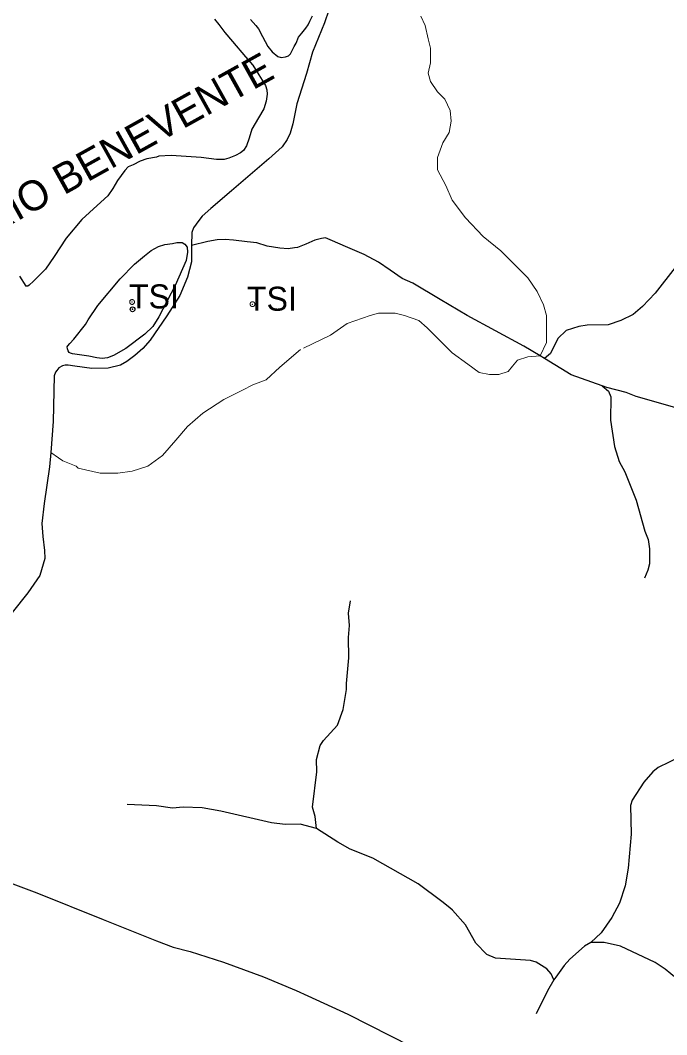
# Model space of a CAD drawing. Extents: x 317.8 to 344.1, y 7676.8 to 7704.8.
# Drawn here: x 328.24 to 330.394, y 7697.935 to 7701.313 of the extents above; entities that cross this region are included whole.
import ezdxf
from ezdxf.enums import TextEntityAlignment as Align

# ---------------------------------------------------------------- set-up
doc = ezdxf.new("R2010")
doc.units = 0
doc.header["$LTSCALE"] = 0.032
doc.header["$PDMODE"] = 32
doc.header["$PDSIZE"] = 0.016
doc.linetypes.add('SHORT_DASHED', pattern=[2.7, 1.5, -1.2])
for name, color, linetype, lineweight in [('2', 7, 'Continuous', 25), ('21', 7, 'SHORT_DASHED', 13), ('7', 7, 'Continuous', 25)]:
    doc.layers.add(name, color=color, linetype=linetype, lineweight=lineweight)
doc.layers.add('54', color=7, linetype='Continuous')
doc.layers.add('61', color=7, linetype='Continuous')

msp = doc.modelspace()

# ---------------------------------------------------------------- linework, layer by layer
at = {"layer": '2'}
for points in [[(329.2171, 7701.5954), (329.2251, 7701.5909), (329.2353, 7701.5818), (329.2524, 7701.5499), (329.2672, 7701.51), (329.2729, 7701.4668), (329.2729, 7701.4087), (329.2672, 7701.3472), (329.2536, 7701.305), (329.2137, 7701.2071), (329.1932, 7701.1365), (329.1613, 7701.0352), (329.1476, 7700.968), (329.1385, 7700.9372), (329.1294, 7700.9167), (329.1123, 7700.8917), (329.0679, 7700.8518), (328.9438, 7700.7459), (328.8743, 7700.6867), (328.8459, 7700.6605), (328.8345, 7700.6468), (328.8163, 7700.6218), (328.8117, 7700.607), (328.8106, 7700.5637)], [(328.8867, 7701.317), (328.9013, 7701.2992), (328.9212, 7701.2723), (328.947, 7701.243), (328.9903, 7701.1915), (329.0149, 7701.1634), (329.0348, 7701.1318), (329.057, 7701.0967), (329.0612, 7701.0814), (329.0617, 7701.0674), (329.0593, 7701.044), (329.0512, 7701.0183), (329.0336, 7700.989), (329.0114, 7700.9504), (329.002, 7700.9211), (328.9938, 7700.8954), (328.9833, 7700.8802), (328.9739, 7700.872), (328.9563, 7700.8626), (328.9341, 7700.8544), (328.9189, 7700.8497), (328.8931, 7700.8497), (328.8428, 7700.8568), (328.7422, 7700.8626)], [(329.0064, 7701.3164), (329.0247, 7701.2959), (329.0338, 7701.2845), (329.0463, 7701.2595), (329.0645, 7701.2265), (329.0793, 7701.2083), (329.0975, 7701.1923), (329.1089, 7701.19), (329.1237, 7701.1912), (329.1328, 7701.1946), (329.1397, 7701.2014), (329.142, 7701.206), (329.1522, 7701.2265), (329.159, 7701.2367), (329.167, 7701.2572), (329.1773, 7701.2709), (329.1909, 7701.2868), (329.1989, 7701.2982), (329.2046, 7701.3107), (329.2137, 7701.3278)], [(328.7422, 7700.8626), (328.7012, 7700.8603), (328.693, 7700.8579), (328.6614, 7700.8521), (328.6392, 7700.8439), (328.6157, 7700.8322)], [(328.6157, 7700.8322), (328.5994, 7700.8252), (328.5877, 7700.8135), (328.5631, 7700.7795), (328.5479, 7700.7526), (328.5315, 7700.7292), (328.4952, 7700.6964), (328.4449, 7700.6496), (328.3922, 7700.5876), (328.3524, 7700.5267), (328.3231, 7700.4846), (328.2833, 7700.4442), (328.2688, 7700.431), (328.2648, 7700.4282), (328.2615, 7700.4276), (328.2576, 7700.4284)], [(328.8106, 7700.5637), (328.8106, 7700.509), (328.7969, 7700.4578), (328.7707, 7700.3963), (328.7274, 7700.3291), (328.6728, 7700.2483), (328.6477, 7700.2198), (328.6215, 7700.197), (328.5942, 7700.1765), (328.5737, 7700.1651), (328.5327, 7700.1549), (328.478, 7700.1537), (328.4211, 7700.1617), (328.3995, 7700.1651), (328.3892, 7700.1651), (328.3801, 7700.1629), (328.3676, 7700.156), (328.3608, 7700.1469), (328.3573, 7700.1412), (328.3528, 7700.1287), (328.3494, 7699.9772), (328.3408, 7699.8737)], [(328.2373, 7700.4609), (328.2576, 7700.4284)], [(328.3408, 7699.8737), (328.3368, 7699.8258), (328.3186, 7699.7039), (328.3118, 7699.6379), (328.3152, 7699.5946), (328.3198, 7699.5479), (328.3209, 7699.5206), (328.3163, 7699.5024), (328.305, 7699.4637), (328.2651, 7699.4067), (328.2127, 7699.3407)], [(328.0088, 7698.5018), (328.0345, 7698.4948), (328.1338, 7698.4678), (328.295, 7698.4078), (328.516, 7698.319), (328.6937, 7698.2477), (328.7485, 7698.226), (328.8053, 7698.2116), (328.9169, 7698.1764), (329.0501, 7698.1279), (329.1586, 7698.0824), (329.1976, 7698.0644), (329.3311, 7698.0029), (329.5429, 7697.8954)]]:
    msp.add_lwpolyline(points, dxfattribs=at)
msp.add_lwpolyline([(328.4974, 7700.3635), (328.572, 7700.4518), (328.6203, 7700.5015), (328.6534, 7700.5291), (328.6755, 7700.5471), (328.7003, 7700.5595), (328.721, 7700.5664), (328.7473, 7700.5705), (328.7611, 7700.5733), (328.779, 7700.5733), (328.7873, 7700.5678), (328.7956, 7700.5581), (328.7969, 7700.5415), (328.7928, 7700.5139), (328.7555, 7700.4297), (328.7017, 7700.3262), (328.681, 7700.2931), (328.6548, 7700.2683), (328.5913, 7700.2199), (328.5499, 7700.1965), (328.5306, 7700.1896), (328.5127, 7700.1875), (328.4947, 7700.1896), (328.4684, 7700.1951), (328.4367, 7700.1992), (328.4132, 7700.202), (328.4064, 7700.2046), (328.4022, 7700.2075), (328.3988, 7700.2122), (328.3968, 7700.2188), (328.3962, 7700.2257), (328.3985, 7700.2293), (328.4041, 7700.2365), (328.4179, 7700.2517), (328.4571, 7700.3001), (328.4657, 7700.3152)], close=True, dxfattribs=at)
at = {"layer": '21'}
for points in [[(329.5748, 7701.3273), (329.5887, 7701.2961), (329.599, 7701.2512), (329.606, 7701.22), (329.606, 7701.1716), (329.599, 7701.137), (329.606, 7701.1093), (329.6302, 7701.0747), (329.6544, 7701.0504), (329.6717, 7701.0124), (329.6752, 7700.9778), (329.6683, 7700.9397), (329.6475, 7700.9051), (329.6302, 7700.8567), (329.6302, 7700.8151), (329.6579, 7700.7632), (329.6786, 7700.7148), (329.7236, 7700.6559), (329.7824, 7700.5937), (329.8413, 7700.5452), (329.8932, 7700.4933), (329.9313, 7700.4552), (329.9624, 7700.4102), (329.9832, 7700.3653), (329.9935, 7700.3307), (329.9935, 7700.3064), (329.9935, 7700.2787), (329.9935, 7700.2407), (329.9716, 7700.1954)], [(329.9716, 7700.1954), (329.9313, 7700.1922), (329.8966, 7700.1818), (329.8793, 7700.1611), (329.8655, 7700.1438), (329.8344, 7700.1334), (329.8032, 7700.1334), (329.7686, 7700.1403), (329.7305, 7700.168), (329.6786, 7700.2061), (329.6302, 7700.2545), (329.5956, 7700.2891), (329.5679, 7700.3133), (329.5194, 7700.3307), (329.4883, 7700.3376), (329.4329, 7700.3376), (329.4053, 7700.3307), (329.3291, 7700.303), (329.2738, 7700.2649), (329.1734, 7700.2165), (329.1042, 7700.1576), (329.0592, 7700.1161), (329.0142, 7700.0988), (328.9796, 7700.0815), (328.9173, 7700.0503), (328.8481, 7700.0054), (328.7962, 7699.9604), (328.7581, 7699.9154), (328.7131, 7699.8635), (328.6647, 7699.8289), (328.6128, 7699.8116), (328.5643, 7699.8046), (328.5055, 7699.8046), (328.4328, 7699.822), (328.4259, 7699.8289), (328.3809, 7699.8462), (328.3671, 7699.8566), (328.3408, 7699.8737)]]:
    msp.add_lwpolyline(points, dxfattribs=at)
for p in [(328.6121, 7700.3752), (329.0133, 7700.3679)]:
    msp.add_point(p, dxfattribs=at)
at = {"layer": '54'}
msp.add_point((328.6137, 7700.3509), dxfattribs=at)
at = {"layer": '7'}
for p, q in [((329.9716, 7700.1954), (329.9176, 7700.2279)), ((329.986, 7700.1867), (329.9716, 7700.1954))]:
    msp.add_line(p, q, dxfattribs=at)
for points in [[(329.9176, 7700.2279), (329.7287, 7700.3302), (329.6386, 7700.3832), (329.5475, 7700.438), (329.5117, 7700.4538), (329.4718, 7700.4807), (329.4328, 7700.5077), (329.3854, 7700.5337), (329.3315, 7700.5569), (329.2716, 7700.582), (329.2567, 7700.5894), (329.2428, 7700.5866), (329.2214, 7700.5811), (329.1908, 7700.568), (329.1638, 7700.5569), (329.1536, 7700.555), (329.1327, 7700.5522), (329.1039, 7700.5541), (329.0621, 7700.5615), (329.0277, 7700.5727), (328.9961, 7700.5754), (328.9497, 7700.581), (328.9223, 7700.5838), (328.8959, 7700.5826), (328.8647, 7700.5764), (328.8106, 7700.5637)], [(330.5901, 7700.599), (330.5521, 7700.5887), (330.518, 7700.5741), (330.4634, 7700.537), (330.433, 7700.5098), (330.4213, 7700.4904), (330.3551, 7700.4049), (330.3124, 7700.3604), (330.2822, 7700.334), (330.2402, 7700.3139), (330.1985, 7700.2994), (330.1287, 7700.2979), (330.1009, 7700.293), (330.0589, 7700.2801), (330.0305, 7700.2538), (330.006, 7700.2037), (329.9865, 7700.1871), (329.986, 7700.1867)], [(330.1781, 7700.0957), (330.0749, 7700.1331), (329.986, 7700.1867)], [(330.1781, 7700.0957), (330.1993, 7700.0783), (330.2073, 7700.059), (330.2066, 7699.9814), (330.2193, 7699.8939), (330.2357, 7699.8442), (330.2541, 7699.809), (330.292, 7699.7154), (330.3208, 7699.6121), (330.3314, 7699.5841), (330.3361, 7699.5528), (330.3363, 7699.5032), (330.3311, 7699.4817), (330.3191, 7699.4552)], [(330.8445, 7699.9252), (330.7604, 7699.927), (330.7019, 7699.94), (330.6389, 7699.9633), (330.6067, 7699.9807), (330.5708, 7699.9944), (330.4365, 7700.0198), (330.2922, 7700.0601), (330.2584, 7700.0737), (330.1936, 7700.0901), (330.1781, 7700.0957)], [(329.2261, 7698.622), (329.2219, 7698.6612), (329.2138, 7698.6925), (329.2277, 7698.8101), (329.2269, 7698.8519), (329.239, 7698.8981), (329.2502, 7698.9145), (329.2963, 7698.9661), (329.3157, 7699.0175), (329.3271, 7699.0845), (329.3264, 7699.1041), (329.3344, 7699.1896), (329.3328, 7699.2581), (329.3362, 7699.2982), (329.3337, 7699.3389), (329.3395, 7699.3802)], [(331.1384, 7698.976), (331.1069, 7698.97), (331.0313, 7698.9644), (331.015, 7698.9596), (330.9289, 7698.9547), (330.8748, 7698.9611), (330.7705, 7698.9611), (330.7191, 7698.9685), (330.6609, 7698.9684), (330.5294, 7698.9114), (330.4749, 7698.8777), (330.365, 7698.8244), (330.3476, 7698.8103), (330.3178, 7698.776), (330.2784, 7698.7163), (330.2734, 7698.6979), (330.2751, 7698.6023), (330.2652, 7698.4894), (330.2555, 7698.431), (330.2363, 7698.373), (330.211, 7698.3257), (330.1755, 7698.274), (330.1407, 7698.2419)], [(329.2261, 7698.622), (329.1718, 7698.636), (329.1223, 7698.6352), (329.0766, 7698.6401), (328.908, 7698.6791), (328.8455, 7698.6906), (328.7827, 7698.6923), (328.7471, 7698.689), (328.6939, 7698.6971), (328.5953, 7698.7013)], [(330.018, 7698.1173), (330.0179, 7698.1175), (330.0081, 7698.1379), (329.9944, 7698.1546), (329.9582, 7698.1767), (329.9392, 7698.182), (329.8235, 7698.1902), (329.7945, 7698.2023), (329.7575, 7698.2392), (329.7226, 7698.3007), (329.68, 7698.3491), (329.6707, 7698.3569), (329.6444, 7698.379), (329.5653, 7698.4371), (329.4143, 7698.5227), (329.3391, 7698.553), (329.2972, 7698.5759), (329.2261, 7698.622)], [(330.1407, 7698.2419), (330.1194, 7698.2292), (330.0712, 7698.1869), (330.0515, 7698.1655), (330.0236, 7698.1268), (330.018, 7698.1173)], [(330.7178, 7697.7308), (330.6931, 7697.7578), (330.6708, 7697.794), (330.6556, 7697.8302), (330.6532, 7697.8417), (330.6402, 7697.9038), (330.6225, 7697.9557), (330.6088, 7697.9796), (330.588, 7698.0011), (330.5453, 7698.0338), (330.4827, 7698.0755), (330.3888, 7698.1527), (330.3546, 7698.1749), (330.2399, 7698.2299), (330.1857, 7698.2415), (330.1407, 7698.2419)], [(330.018, 7698.1173), (329.9964, 7698.0805), (329.9589, 7698.0045)]]:
    msp.add_lwpolyline(points, dxfattribs=at)

# ---------------------------------------------------------------- texts
at = {"layer": '61'}
msp.add_text('RIO BENEVENTE', height=0.1, rotation=29.055, dxfattribs=at).set_placement((328.6186, 7700.8598), align=Align.CENTER)
for p in [(328.6017, 7700.3539), (328.9948, 7700.3461)]:
    msp.add_text('TSI', height=0.08, dxfattribs=at).set_placement(p)

doc.saveas('drawing.dxf')
